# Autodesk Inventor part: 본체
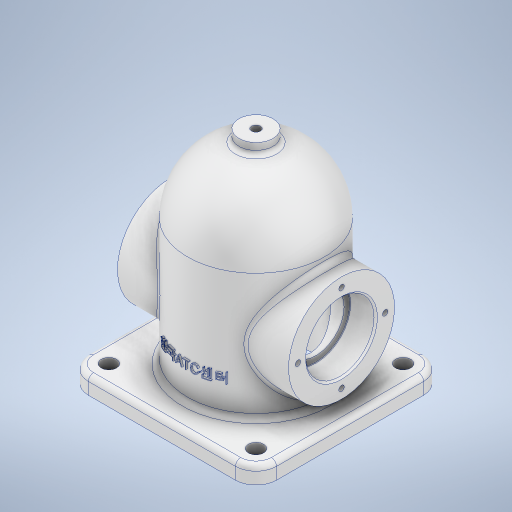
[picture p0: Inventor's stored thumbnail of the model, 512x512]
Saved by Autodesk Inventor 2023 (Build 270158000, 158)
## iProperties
Created: 2025-04
Part Number: 본체
Material: 알루미늄 6061
Document SubType Name: Modeling
Designer: Admin
Density: 2.7 g/cm^3
Appearance: 알루미늄 - 평지
Mass: 865.972 g
Surface Area: 801.981 cm^2
Volume: 320.731 cm^3
Author: Admin
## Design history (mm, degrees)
sketch "스케치1"
  geometry: L1 (-65.941, 0)-(57.657, 0) reference; L2 (-40, 0)-(0, 0); L3 (0, -84)-(-40, -84); L4 (-40, -84)-(-40, 0); L5 (0, -110.457)-(0, 74.741) reference; L6 (0, 40)-(0, -84); A1 r 40 centre (0, 0) between (0, 40) and (-40, 0); 1 further point
  constraints: 8 end point, 4 point on line, 2 point on circle, 1 centre point, 1 coincident, 1 collinear, 1 horizontal, 1 parallel, 1 perpendicular
  dimensions: "d1" = 40 radius of A1; "d2" = 84 distance between parallel lines of L1 L3
revolve "회전1" sketch "스케치1" stored, may be unused: angle "d3" = 90 deg
sketch "스케치3"
  geometry: L1 (-55, -55)-(55, -55); L2 (55, -55)-(55, 55); L3 (55, 55)-(-55, 55); L4 (-55, 55)-(-55, -55); L5 (-55, -55)-(55, 55); L6 (55, -55)-(-55, 55); 1 further point
  constraints: 12 end point, 2 midpoint, 2 parallel, 1 horizontal, 1 perpendicular
  dimensions: "d10" = 110 distance of L2.end L3.end; "d11" = 110 distance of L1.end L2.end
extrude "돌출1" join sketch "스케치3" distance "d12" = 10; taper "d13" = 0 deg
sketch "스케치4"
  geometry: C1 r 10 at (55, -55); 1 further point
  constraints: 1 centre point, 1 coincident
  dimensions: "d14" = 20 diameter of C1
extrude "돌출2" join sketch "스케치4" distance "d15" = 129; taper "d16" = 0 deg
sketch "스케치5"
  geometry: L1 (0, -77)-(0, 77) reference; L2 (-109.8, 0)-(70.8, 0) reference; L3 (-84, 55)-(-84, -55) reference; C1 r 31 at (-36, 0); 1 further point
  constraints: 1 centre point, 1 point on line
  dimensions: "d17" = 62 diameter of C1; "d21" = 48 distance from line of L3 C1.centre
extrude "돌출3" join sketch "스케치5" stored distance "d19" = 100; taper "d20" = 0 deg
sketch "스케치6"
  geometry: L1 (-77, 0)-(77, 0) reference; L2 (40, 0)-(-40, 0) reference; L3 (-32, -84)-(-32, 0); L4 (-32, -84)-(0, -84); L5 (-55, -84)-(55, -84) reference; L6 (0, -109.8)-(0, 70.8) reference; L7 (0, 32)-(0, -84); A1 r 32 centre (0, 0) between (0, 32) and (-32, 0); 1 further point
  constraints: 6 end point, 2 point on circle, 1 centre point, 1 coincident, 1 collinear, 1 midpoint, 1 point on line
  dimensions: "d22" = 32 radius of A1; "d23" = 84 distance of L3.start L3.end; "d25" = 32 distance of L3.start L4.end
revolve "회전3" sketch "스케치6" stored, may be unused: angle "d26" = 90 deg
sketch "스케치7"
  geometry: L1 (0, -73.8)-(0, 106.8) reference; L2 (77, 36)-(-77, 36) reference; C1 r 20 at (0, 0); C2 r 31 at (0, 0) reference; 1 further point
  constraints: 1 centre point, 1 concentric, 1 point on line
  dimensions: "d27" = 40 diameter of C1
extrude "돌출4" cut sketch "스케치7" distance "d28" = 15; taper "d29" = 0 deg
sketch "스케치8"
  geometry: C1 r 16.5 at (0, 0); C2 r 31 at (0, 0) reference; 1 further point
  constraints: 1 centre point, 1 concentric
  dimensions: "d30" = 33 diameter of C1
extrude "돌출5" cut sketch "스케치8" stored distance "d31" = 15; taper "d32" = 0 deg
sketch "스케치9" dims "d33" = 51
  geometry: L1 (0, -73.8)-(0, 106.8) reference; L2 (-77, 36)-(77, 36) reference; C1 r 31 at (0, 0) reference; 3 further points
  constraints: 1 point on line, 1 vertical alignment, 3 other
hole "구멍1" sketch "스케치9" at (0, 25.5) diameter "d34" = 3.242; stored, may be unused: countersink angle "d38" = 90 deg, drill point angle "d40" = 118 deg; dims "d35" = 8, "d36" = 4, "d37" = 2, "d39" = 10
sketch "스케치10"
  geometry: 2 further points
  constraints: 1 coincident
hole "구멍2" sketch "스케치10" at (0, 0) diameter "d44" = 5.1881; stored, may be unused: countersink angle "d48" = 90 deg, drill point angle "d50" = 0 deg; dims "d45" = 15, "d46" = 4, "d47" = 2, "d49" = 12
fillet "모깎기1" dims "d51" = 12
sketch "스케치11"
  geometry: C1 r 4.5 at (-43, 43); A1 r 12 centre (-43, 43) between (-43, 55) and (-55, 43) reference; 1 further point
  constraints: 1 centre point, 1 concentric
  dimensions: "d53" = 9 diameter of C1
extrude "돌출6" cut sketch "스케치11" stored distance "d54" = 10; taper "d55" = 0 deg
fillet "모깎기2" dims "d56" = 3
fillet "모깎기3" dims "d57" = 3
fillet "모깎기4" dims "d58" = 3
fillet "모깎기5" dims "d59" = 3
fillet "모깎기6" dims "d60" = 0.3
chamfer "모따기1" distance "d61" = 1; stored, may be unused: second distance "d62" = 2, angle "d63" = 45 deg
node "작업 평면1"
sketch "스케치12"
  geometry: L1 (0, -109.8)-(0, 70.8) reference; L2 (-77, 0)-(77, 0) reference; L3 (43, -84)-(-43, -84) reference; 2 further points
  constraints: 1 point on line, 1 other
  dimensions: "d65" = 30 distance from line of L3 point (0, -54)
feature "엠보싱1" sketch "스케치12" dims "d14" = 20, "d66" = 1, "d67" = 0
node "솔리드1"
mirror "미러1"
pattern_circular "원형 패턴1" dims angle "d42" = 360 deg
mirror "미러2"
mirror "미러3"
mirror "미러4"
feature "A9D066F2-1C7D-4E18-AEED-F7BC21143FA4" dims "d34" = 3.242, "d35" = 8, "d36" = 4, "d37" = 2, "d38" = 90 deg, "d39" = 10, "d40" = 118 deg
other parameters: "d64" = 110.25
